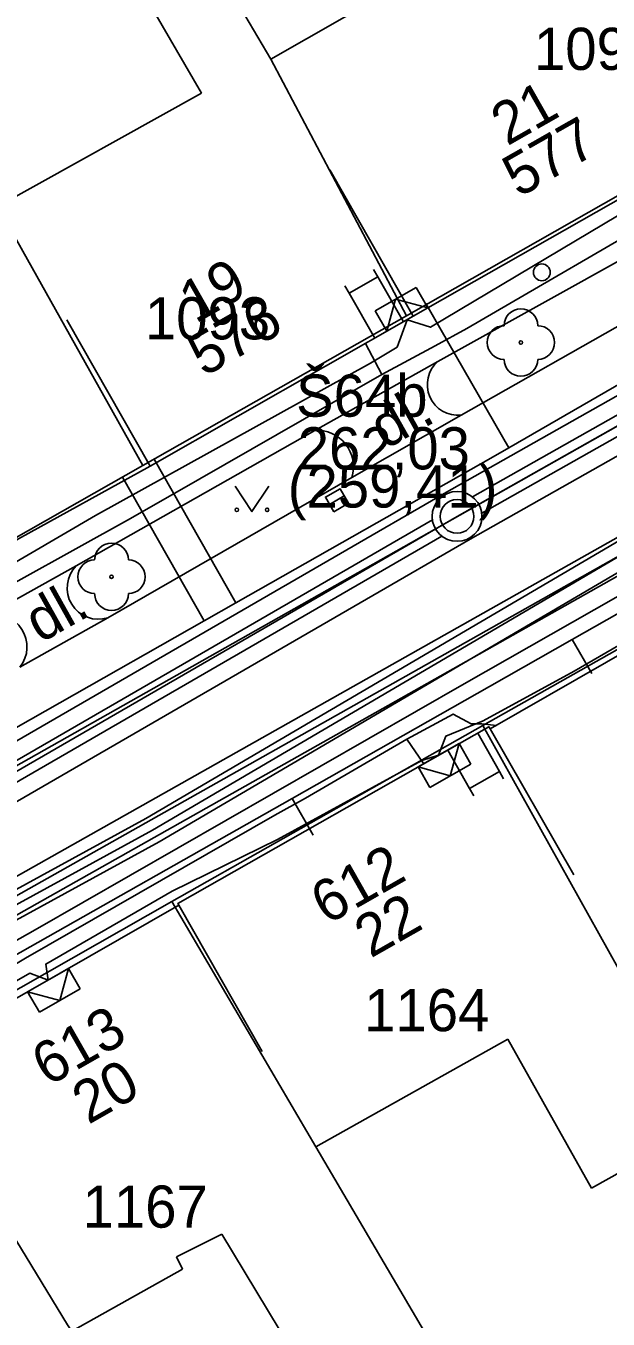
# Model space of a CAD drawing. Extents: x -601580 to 4, y -1204314 to 4.
# Drawn here: x -599889.35 to -599872.06, y -1203379.09 to -1203340.72 of the extents above; entities that cross this region are included whole.
import ezdxf

# ---------------------------------------------------------------- set-up
doc = ezdxf.new("R2010")
doc.units = 0
for name, color, linetype in [('00-EON NN', 7, 'Continuous'), ('00-INNOGY-NTL', 7, 'Continuous'), ('00-KN-HRANICE PARCEL', 7, 'Continuous'), ('00-KN-PARC. CISLA', 7, 'Continuous'), ('00-KN-VNITRNI KRESBA', 7, 'Continuous'), ('00-POLOHOPIS', 7, 'Continuous'), ('00-SITE KOM. KABEL', 7, 'Continuous'), ('00-VODOVOD STAVAJICI', 7, 'Continuous'), ('11-REKONSTRUKCE  VYKOP', 7, 'Continuous'), ('11-REKONSTRUKCE KANALIZACE', 7, 'Continuous'), ('11-REKONSTRUKCE KANALIZACE OSA', 7, 'Continuous'), ('11-REKONSTRUKCE VODOVOD', 7, 'Continuous'), ('11-REKONSTRUKCE VODOVODU VYKOP', 7, 'Continuous'), ('11-VAK-KANAL PUVODNI', 7, 'Continuous'), ('14', 7, 'Continuous'), ('Vrstva 22', 7, 'Continuous'), ('Vrstva 26', 7, 'Continuous'), ('Vrstva 27', 7, 'Continuous'), ('Vrstva 28', 7, 'Continuous'), ('Vrstva 36', 7, 'Continuous'), ('Vrstva 6', 7, 'Continuous'), ('Vrstva 9', 7, 'Continuous')]:
    doc.layers.add(name, color=color, linetype=linetype)

# ---------------------------------------------------------------- blocks, each defined once
blk = doc.blocks.new('VCHOD_1272')
at = {"layer": 'Vrstva 6'}
blk.add_line((0, 0.249), (0, 0), dxfattribs=at)
blk = doc.blocks.new('VCHOD_1274')
at = {"layer": 'Vrstva 6'}
blk.add_line((0, 0.249), (0, 0), dxfattribs=at)
blk = doc.blocks.new('3.14_442')
at = {"layer": 'Vrstva 36'}
blk.add_lwpolyline([(-0.5, 0.75), (0, 0), (0.5, 0.75)], dxfattribs=at)
for centre in [(-0.45, 0.05), (0.449, 0.05)]:
    blk.add_circle(centre, 0.05, dxfattribs=at)
blk = doc.blocks.new('3.13_848')
at = {"layer": 'Vrstva 22'}
blk.add_circle((0, 0), 0.05, dxfattribs=at)
for centre, start, end in [((0, 0.5), 0, 180), ((-0.5, 0), 90, 270), ((0.5, 0), 270, 90), ((0, -0.5), 180, 0)]:
    blk.add_arc(centre, 0.5, start, end, dxfattribs=at)
blk = doc.blocks.new('3.13_850')
at = {"layer": 'Vrstva 22'}
blk.add_circle((0, 0), 0.05, dxfattribs=at)
for centre, start, end in [((0, 0.5), 0, 180), ((-0.5, 0), 90, 270), ((0.5, 0), 270, 90), ((0, -0.5), 180, 0)]:
    blk.add_arc(centre, 0.5, start, end, dxfattribs=at)
blk = doc.blocks.new('6.30_434')
at = {"layer": 'Vrstva 27'}
blk.add_line((-0.25, 0), (0.25, 0), dxfattribs=at)
blk.add_lwpolyline([(-0.25, -0.25), (0.25, -0.25), (0.25, 0.25), (-0.25, 0.25)], close=True, dxfattribs=at)
blk = doc.blocks.new('6.14A_1138')
at = {"layer": 'Vrstva 28'}
blk.add_circle((0, 0), 0.25, dxfattribs=at)
blk = doc.blocks.new('VCHOD_1324')
at = {"layer": 'Vrstva 6'}
blk.add_line((0, 0.25), (0, 0), dxfattribs=at)
blk = doc.blocks.new('VCHOD_1326')
at = {"layer": 'Vrstva 6'}
blk.add_line((0, 0.25), (0, 0), dxfattribs=at)
blk = doc.blocks.new('NN630')
at = {"layer": 'Vrstva 9'}
for points in [[(-3, -700), (-703, 0)], [(-703, -700), (-703, 0), (697, 0), (697, -700)], [(-3, -700), (697, 0)], [(-703, -700), (697, -700)]]:
    blk.add_lwpolyline(points, dxfattribs=at)

msp = doc.modelspace()

# ---------------------------------------------------------------- linework, layer by layer
at = {"layer": '00-EON NN'}
for points in [[(-599916.36, -1203371.79), (-599916.209, -1203371.08), (-599915.81, -1203371.46), (-599910.07, -1203368.2), (-599904.06, -1203364.78), (-599903.801, -1203364.07), (-599903.24, -1203364.29), (-599898.81, -1203361.82), (-599898.704, -1203361.203), (-599898.17, -1203361.35), (-599891.07, -1203357.23), (-599890.879, -1203356.706), (-599890.29, -1203357), (-599887.28, -1203355.25), (-599879.12, -1203350.73), (-599878.33, -1203350.25), (-599878.031, -1203349.435), (-599877.34, -1203349.66), (-599870.9, -1203345.83)], [(-599907.869, -1203379.935), (-599907.992, -1203379.738), (-599907.81, -1203379.31), (-599902.52, -1203376.44), (-599896.41, -1203372.98), (-599895.903, -1203373.085), (-599895.88, -1203372.67), (-599892.7, -1203370.81), (-599889.23, -1203368.83), (-599888.687, -1203369.031), (-599888.76, -1203368.56), (-599885.01, -1203366.39), (-599881.88, -1203364.86), (-599877.59, -1203362.52), (-599877.095, -1203362.361), (-599876.88, -1203361.79), (-599875.77, -1203361.34), (-599873.07, -1203359.87), (-599870.56, -1203358.41)]]:
    msp.add_lwpolyline(points, dxfattribs=at)
at = {"layer": '00-INNOGY-NTL'}
for p, q in [((-599877.48, -1203348.96), (-599875.01, -1203353.24)), ((-599885.54, -1203353.57), (-599883.12, -1203357.84)), ((-599886.48, -1203354.11), (-599884.06, -1203358.37)), ((-599875.59, -1203360.32), (-599873.13, -1203358.93)), ((-599873.13, -1203358.93), (-599872.55, -1203359.94)), ((-599881.44, -1203363.64), (-599880.82, -1203364.73))]:
    msp.add_line(p, q, dxfattribs=at)
for points in [[(-599918.93, -1203378.19), (-599915.5, -1203376.2), (-599912.83, -1203374.69), (-599907.37, -1203371.6), (-599896.09, -1203365.2), (-599892.64, -1203363.24), (-599884.06, -1203358.37), (-599883.12, -1203357.84), (-599875.48, -1203353.51), (-599875.01, -1203353.24), (-599855.55, -1203342.01), (-599842.38, -1203334.41), (-599839.91, -1203332.99), (-599825.89, -1203324.64), (-599823.19, -1203319.4)], [(-599873.13, -1203358.93), (-599861.72, -1203352.46), (-599861.11, -1203353.55)], [(-599892.64, -1203363.24), (-599890.04, -1203368.51), (-599881.44, -1203363.64), (-599875.59, -1203360.32)]]:
    msp.add_lwpolyline(points, dxfattribs=at)
at = {"layer": '00-KN-HRANICE PARCEL'}
for p, q in [((-599878.05, -1203349.32), (-599882.08, -1203341.7)), ((-599878.05, -1203349.32), (-599866.74, -1203342.89)), ((-599885.88, -1203353.76), (-599878.05, -1203349.32)), ((-599894.54, -1203358.68), (-599885.88, -1203353.76)), ((-599865.39, -1203355.6), (-599875.78, -1203361.48)), ((-599875.78, -1203361.48), (-599885.02, -1203366.7)), ((-599885.02, -1203366.7), (-599893, -1203371.24))]:
    msp.add_line(p, q, dxfattribs=at)
for points in [[(-599882.08, -1203341.7), (-599883.36, -1203339.52), (-599884.56, -1203337.47), (-599885.07, -1203336.61), (-599886.24, -1203334.61), (-599887.22, -1203332.94), (-599889.74, -1203328.53)], [(-599885.88, -1203353.76), (-599890.19, -1203346.08), (-599892.87, -1203341.39)], [(-599875.78, -1203361.48), (-599869.18, -1203373.31), (-599866.45, -1203378.2)], [(-599885.02, -1203366.7), (-599880.74, -1203373.98), (-599877.05, -1203380.26), (-599874.74, -1203384.21)], [(-599893, -1203371.24), (-599888.11, -1203379.26), (-599887.99, -1203379.45), (-599883.33, -1203387.6)]]:
    msp.add_lwpolyline(points, dxfattribs=at)
at = {"layer": '00-KN-VNITRNI KRESBA'}
for p, q in [((-599882.08, -1203341.7), (-599873.61, -1203336.87)), ((-599887.04, -1203337.71), (-599884.14, -1203342.71)), ((-599890.19, -1203346.08), (-599884.14, -1203342.71)), ((-599875.04, -1203370.79), (-599880.74, -1203373.98)), ((-599872.56, -1203375.21), (-599875.04, -1203370.79)), ((-599869.18, -1203373.31), (-599872.56, -1203375.21)), ((-599884.88, -1203377.25), (-599883.53, -1203376.57)), ((-599883.53, -1203376.57), (-599880.59, -1203381.44)), ((-599884.7, -1203377.61), (-599884.88, -1203377.25)), ((-599887.99, -1203379.45), (-599884.7, -1203377.61))]:
    msp.add_line(p, q, dxfattribs=at)
at = {"layer": '00-POLOHOPIS'}
for p, q in [((-599869.795, -1203346.598), (-599877.116, -1203350.672)), ((-599876.426, -1203352.268), (-599868.782, -1203347.937)), ((-599879.754, -1203348.644), (-599878.904, -1203348.159)), ((-599857.327, -1203349.414), (-599876.335, -1203360.239)), ((-599877.116, -1203350.672), (-599880.775, -1203352.722)), ((-599879.674, -1203354.123), (-599876.426, -1203352.268)), ((-599880.775, -1203352.722), (-599887.855, -1203356.741)), ((-599886.917, -1203358.283), (-599879.674, -1203354.123)), ((-599887.855, -1203356.741), (-599890.519, -1203358.225)), ((-599889.53, -1203359.746), (-599886.917, -1203358.283)), ((-599876.335, -1203360.239), (-599889.073, -1203367.538)), ((-599876.176, -1203363.346), (-599875.288, -1203362.842)), ((-599889.073, -1203367.538), (-599902.638, -1203375.189))]:
    msp.add_line(p, q, dxfattribs=at)
for points in [[(-599869.022, -1203338.561), (-599866.551, -1203342.907), (-599877.853, -1203349.333), (-599880.324, -1203344.986)], [(-599880.324, -1203344.986), (-599877.853, -1203349.333), (-599885.661, -1203353.785), (-599888.138, -1203349.442)], [(-599878.141, -1203349.497), (-599878.904, -1203348.159), (-599879.754, -1203348.644), (-599878.991, -1203349.982)], [(-599888.138, -1203349.442), (-599885.661, -1203353.785), (-599889.565, -1203355.935), (-599894.334, -1203358.734), (-599896.812, -1203354.391)], [(-599862.761, -1203360), (-599865.205, -1203355.638), (-599875.567, -1203361.574), (-599873.082, -1203365.912)], [(-599873.082, -1203365.912), (-599875.567, -1203361.574), (-599875.602, -1203361.513), (-599884.842, -1203366.763), (-599884.812, -1203366.815), (-599882.33, -1203371.156)], [(-599875.936, -1203361.702), (-599875.288, -1203362.842), (-599876.176, -1203363.346), (-599876.824, -1203362.207)], [(-599882.33, -1203371.156), (-599884.812, -1203366.815), (-599892.679, -1203371.314), (-599890.197, -1203375.654)]]:
    msp.add_lwpolyline(points, dxfattribs=at)
for centre, radius, start, end in [((-599876.521, -1203351.362), 0.911, 130.775, 275.9856), ((-599880.707, -1203353.801), 1.082, 342.7088, 93.6165), ((-599887.196, -1203357.397), 0.929, 135.1308, 287.4936), ((-599890.269, -1203359.144), 0.953, 320.8581, 105.2081)]:
    msp.add_arc(centre, radius, start, end, dxfattribs=at)
at = {"layer": '00-SITE KOM. KABEL'}
for points in [[(-599878.78, -1203351.06), (-599877.2, -1203350.21), (-599876.26, -1203349.7), (-599869.99, -1203346.06), (-599870.48, -1203345.14)], [(-599877.2, -1203350.21), (-599876.26, -1203349.7)], [(-599879.27, -1203350.14), (-599878.78, -1203351.06)], [(-599891.21, -1203358.09), (-599886.24, -1203355.34), (-599884.19, -1203354.16), (-599878.78, -1203351.06)], [(-599886.24, -1203355.34), (-599884.19, -1203354.16)], [(-599878.04, -1203361.88), (-599876.66, -1203361.14), (-599876.13, -1203361.43), (-599875.81, -1203361.43), (-599875.38, -1203361.48)], [(-599876.66, -1203361.14), (-599876.13, -1203361.43)], [(-599878.04, -1203361.88), (-599881.05, -1203363.63), (-599881.96, -1203364.14), (-599889.36, -1203368.38), (-599890.21, -1203368.89), (-599890.5, -1203369.1)], [(-599877.54, -1203362.61), (-599878.04, -1203361.88)], [(-599881.05, -1203363.63), (-599881.96, -1203364.14)]]:
    msp.add_lwpolyline(points, dxfattribs=at)
at = {"layer": '00-VODOVOD STAVAJICI'}
msp.add_lwpolyline([(-599802.972, -1203313.691), (-599814.8, -1203324.017), (-599839.265, -1203338.126), (-599866.154, -1203353.178), (-599885.591, -1203364.585), (-599905.396, -1203375.418)], dxfattribs=at)
at = {"layer": '11-REKONSTRUKCE  VYKOP'}
for points in [[(-600012.747, -1203435.048), (-599974.752, -1203413.595), (-599940.464, -1203394.405), (-599905.641, -1203374.982), (-599839.513, -1203337.692), (-599815.093, -1203323.609), (-599803.159, -1203313.09)], [(-600012.255, -1203435.918), (-599974.261, -1203414.467), (-599939.977, -1203395.278), (-599905.151, -1203375.854), (-599839.017, -1203338.56), (-599814.507, -1203324.425), (-599802.497, -1203313.84)], [(-600007.288, -1203428.801), (-599963.695, -1203404.318), (-599920.22, -1203379.63), (-599876.936, -1203354.596), (-599839.594, -1203333.492)], [(-600006.524, -1203430.161), (-599962.927, -1203405.676), (-599919.444, -1203380.984), (-599876.162, -1203355.95), (-599838.826, -1203334.851)]]:
    msp.add_lwpolyline(points, dxfattribs=at)
at = {"layer": '11-REKONSTRUKCE KANALIZACE'}
for points in [[(-599876.091, -1203354.692), (-599840.927, -1203334.82)], [(-599875.815, -1203355.179), (-599840.652, -1203335.308)], [(-599919.379, -1203379.722), (-599877.282, -1203355.373)], [(-599919.099, -1203380.207), (-599877.002, -1203355.858)]]:
    msp.add_lwpolyline(points, dxfattribs=at)
for radius in [0.74, 0.5]:
    msp.add_circle((-599876.549, -1203355.273), radius, dxfattribs=at)
at = {"layer": '11-REKONSTRUKCE KANALIZACE OSA'}
msp.add_lwpolyline([(-600006.906, -1203429.481), (-599963.311, -1203404.997), (-599919.832, -1203380.307), (-599876.549, -1203355.273), (-599840.193, -1203334.727)], dxfattribs=at)
at = {"layer": '11-REKONSTRUKCE VODOVOD'}
msp.add_lwpolyline([(-600012.501, -1203435.483), (-599974.506, -1203414.031), (-599940.22, -1203394.841), (-599905.396, -1203375.418), (-599839.265, -1203338.126), (-599814.8, -1203324.017), (-599802.828, -1203313.465)], dxfattribs=at)
at = {"layer": '11-REKONSTRUKCE VODOVODU VYKOP'}
for points in [[(-599803.235, -1203313.39), (-599815.034, -1203323.69), (-599839.463, -1203337.778), (-599866.353, -1203352.831), (-599885.788, -1203364.237), (-599905.588, -1203375.067)], [(-599802.709, -1203313.992), (-599814.566, -1203324.344), (-599839.067, -1203338.474), (-599865.955, -1203353.525), (-599885.394, -1203364.933), (-599905.204, -1203375.769)]]:
    msp.add_lwpolyline(points, dxfattribs=at)
at = {"layer": '11-VAK-KANAL PUVODNI'}
msp.add_lwpolyline([(-599951.36, -1203397.55), (-599840.193, -1203334.727)], dxfattribs=at)
at = {"layer": '14'}
msp.add_line((-599881.44, -1203363.64), (-599880.82, -1203364.73), dxfattribs=at)

# ---------------------------------------------------------------- block references
at = {"layer": '00-POLOHOPIS'}
for name, p, xscale, yscale, rotation in [('VCHOD_1326', (-599878.904, -1203348.159), 1.00000093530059, 1.00000093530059, 29.70864443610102), ('6.14A_1138', (-599874.03, -1203348.03), 0.99999896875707, 0.99999896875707, 29.215351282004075), ('VCHOD_1324', (-599879.754, -1203348.644), 1.00000093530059, 1.00000093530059, 29.70864443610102), ('6.30_434', (-599880.116, -1203354.792), 0.99999968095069, 0.9999996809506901, 29.870701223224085), ('VCHOD_1274', (-599875.288, -1203362.842), 0.9999992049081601, 0.99999920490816, -150.42207352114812), ('VCHOD_1272', (-599876.176, -1203363.346), 0.9999992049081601, 0.99999920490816, -150.42207352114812)]:
    msp.add_blockref(name, p, dxfattribs=dict(at, xscale=xscale, yscale=yscale, rotation=rotation))
for name, p in [('3.13_850', (-599874.653, -1203350.113)), ('3.14_442', (-599882.637, -1203355.128)), ('3.13_848', (-599886.808, -1203357.065))]:
    msp.add_blockref(name, p, dxfattribs=at)
at = {"layer": 'Vrstva 26', "xscale": 0.001, "yscale": 0.0010000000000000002}
for p, rotation in [((-599878.031, -1203349.435), -150.30879447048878), ((-599877.095, -1203362.361), 29.60456666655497), ((-599888.687, -1203369.031), 29.764572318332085)]:
    msp.add_blockref('NN630', p, dxfattribs=dict(at, rotation=rotation))

# ---------------------------------------------------------------- texts
at = {"layer": '00-KN-PARC. CISLA'}
for s, p in [('1094', (-599874.265, -1203342.023)), ('1093', (-599885.817, -1203350.02)), ('1164', (-599879.307, -1203370.55)), ('1167', (-599887.667, -1203376.38))]:
    msp.add_text(s, height=1.25, dxfattribs=at).set_placement(p)
at = {"layer": '00-POLOHOPIS'}
for s, rotation, p in [('21', 29.6201, (-599875.06, -1203344.294)), ('577', 29.6201, (-599874.719, -1203345.826)), ('19', 29.6911, (-599884.316, -1203349.565)), ('576', 29.6911, (-599884.061, -1203351.145)), ('dl.', 29.2737, (-599878.68, -1203353.303)), ('dl.', 29.2737, (-599888.925, -1203359.048)), ('612', 29.6044, (-599880.414, -1203367.41)), ('22', 29.6044, (-599879.115, -1203368.397)), ('613', 29.761, (-599888.696, -1203372.204)), ('20', 29.761, (-599887.495, -1203373.334))]:
    msp.add_text(s, height=1.25, rotation=rotation, dxfattribs=at).set_placement(p)
at = {"layer": '11-REKONSTRUKCE KANALIZACE'}
for s, p in [('Š64b', (-599881.328, -1203352.314)), ('262,03 ', (-599881.279, -1203353.877)), ('(259,41)', (-599881.576, -1203355.011))]:
    msp.add_text(s, height=1.25, dxfattribs=at).set_placement(p)

doc.saveas('drawing.dxf')
